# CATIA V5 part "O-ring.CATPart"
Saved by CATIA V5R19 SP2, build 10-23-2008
Part number: O-ring
Definition: O-ring
Nomenclature: O-ring
Source: Unknown
Bounding box of the stored display mesh (mm): x -12.75 to 12.75, y -12.75 to 12.75, z 0 to 1.5
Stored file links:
  Z:\fausse table rondelle-20220905T211342Z-001\fausse table rondelle\O-ring.CATPart
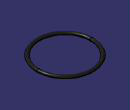
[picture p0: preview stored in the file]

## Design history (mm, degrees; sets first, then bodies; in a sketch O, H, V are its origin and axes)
AxisSystem1: origin (0, 0, 0), X (1, 0, 0), Y (0, 1, 0), Z (0, 0, 1)
Body1 "O-ring" (main body)
  Solid1: solid without history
